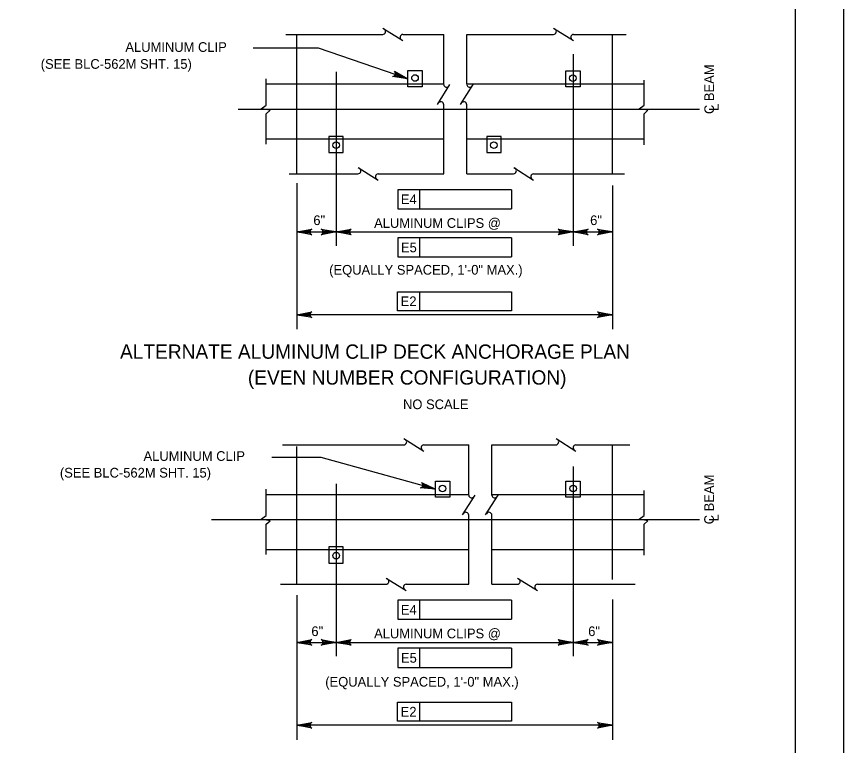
# Model space of a CAD drawing. Extents: x 638263 to 640391, y 293683 to 298655.
# Drawn here: x 639861.3 to 640117.5, y 295708.4 to 295934.1 of the extents above; entities that cross this region are included whole.
import ezdxf

# ---------------------------------------------------------------- set-up
doc = ezdxf.new("R2010")
doc.units = 0
for name, color, linetype in [('2', 7, 'Continuous'), ('3', 7, 'Continuous'), ('4', 7, 'Continuous'), ('8', 7, 'Continuous'), ('9', 7, 'Continuous'), ('PLT-BNDY', 7, 'Continuous')]:
    doc.layers.add(name, color=color, linetype=linetype)

msp = doc.modelspace()

# ---------------------------------------------------------------- linework, layer by layer
at = {"layer": '2'}
for p, q in [((640102.46, 296044.46), (640102.46, 295480.46)), ((639948.08, 295885.4), (639948.08, 295928.58)), ((640045.92, 295885.4), (640045.92, 295928.58)), ((639948.08, 295758.28), (639948.08, 295800.94)), ((640045.92, 295759.8), (640045.92, 295801.5))]:
    msp.add_line(p, q, dxfattribs=at)
at = {"layer": '3'}
for p, q in [((639974.77, 295930.52), (639980.92, 295926.65)), ((640027.67, 295930.52), (640033.82, 295926.65)), ((639944.64, 295928.58), (639974.69, 295928.58)), ((639980.91, 295928.58), (639993.61, 295928.58)), ((639993.61, 295913.01), (639993.61, 295928.58)), ((640000.76, 295913.01), (640000.76, 295928.58)), ((640000.76, 295928.58), (640027.59, 295928.58)), ((640033.81, 295928.58), (640050.15, 295928.58)), ((639938.58, 295906.7), (639938.58, 295914.8)), ((640055.66, 295906.7), (640055.66, 295914.42)), ((639938.58, 295913.23), (639993.61, 295913.23)), ((639991.67, 295906.86), (639995.54, 295913.02)), ((639998.83, 295906.86), (640002.7, 295913.02)), ((640000.76, 295913.23), (640055.66, 295913.23)), ((639937.04, 295905.51), (639938.58, 295906.7)), ((639993.61, 295885.4), (639993.61, 295906.79)), ((640000.76, 295885.4), (640000.76, 295906.79)), ((640054.12, 295905.51), (640055.66, 295906.7)), ((639939.8, 295905.08), (639937.04, 295905.51)), ((639938.58, 295903.99), (639939.8, 295905.08)), ((639938.58, 295894.57), (639938.58, 295903.99)), ((640056.88, 295905.08), (640054.12, 295905.51)), ((640055.66, 295903.99), (640056.88, 295905.08)), ((640055.66, 295894.38), (640055.66, 295903.99)), ((639993.61, 295896.11), (639938.58, 295896.11)), ((640055.66, 295896.11), (640000.76, 295896.11)), ((639945.69, 295885.4), (639967.04, 295885.4)), ((639967.11, 295887.33), (639973.27, 295883.46)), ((639973.26, 295885.4), (639993.61, 295885.4)), ((640000.76, 295885.4), (640015.22, 295885.4)), ((640015.29, 295887.33), (640021.45, 295883.46)), ((640021.44, 295885.4), (640049.62, 295885.4)), ((639981.29, 295803.4), (639987.45, 295799.53)), ((640028.41, 295803.4), (640034.57, 295799.53)), ((639943.68, 295801.46), (639981.22, 295801.46)), ((639987.44, 295801.46), (640001.37, 295801.46)), ((640001.37, 295785.88), (640001.37, 295801.46)), ((640008.53, 295801.46), (640028.34, 295801.46)), ((640008.53, 295785.88), (640008.53, 295801.46)), ((640034.56, 295801.46), (640051.22, 295801.46)), ((639938.58, 295779.58), (639938.58, 295787.68)), ((639938.58, 295786.11), (640001.37, 295786.11)), ((639999.43, 295779.74), (640003.3, 295785.9)), ((640006.59, 295779.74), (640010.46, 295785.9)), ((640008.53, 295786.11), (640055.66, 295786.11)), ((640055.66, 295779.58), (640055.66, 295787.3)), ((639937.04, 295778.39), (639938.58, 295779.58)), ((639939.8, 295777.96), (639937.04, 295778.39)), ((639938.58, 295776.87), (639939.8, 295777.96)), ((640001.37, 295758.28), (640001.37, 295779.67)), ((640008.53, 295758.28), (640008.53, 295779.67)), ((640054.12, 295778.39), (640055.66, 295779.58)), ((640056.88, 295777.96), (640054.12, 295778.39)), ((640055.66, 295776.87), (640056.88, 295777.96)), ((639938.58, 295767.45), (639938.58, 295776.87)), ((640055.66, 295767.26), (640055.66, 295776.87)), ((640001.37, 295768.99), (639938.58, 295768.99)), ((640055.66, 295768.99), (640008.53, 295768.99)), ((639975.79, 295760.21), (639981.95, 295756.34)), ((640016.49, 295760.21), (640022.65, 295756.34)), ((639942.99, 295758.28), (639975.72, 295758.28)), ((639981.94, 295758.28), (640001.37, 295758.28)), ((640008.53, 295758.28), (640016.42, 295758.28)), ((640022.64, 295758.28), (640052.96, 295758.28))]:
    msp.add_line(p, q, dxfattribs=at)
for centre in [(639984.71, 295915.07), (640033.63, 295915.01), (639960.25, 295894.26), (640009.17, 295894.26), (639993.26, 295787.95), (640033.69, 295787.95), (639960.25, 295767.14)]:
    msp.add_circle(centre, 1.02, dxfattribs=at)
for centre, start, end in [((639974.69, 295929.49), 270, 60), ((640027.59, 295929.49), 270, 60), ((639980.99, 295927.68), 95.3286, 237.8672), ((640033.89, 295927.68), 95.3286, 237.8672), ((639994.51, 295913.09), 185.3286, 327.8672), ((640001.67, 295913.09), 185.3286, 327.8672), ((639992.7, 295906.79), 0, 150), ((639999.85, 295906.79), 0, 150), ((639967.04, 295886.31), 270, 60), ((639973.34, 295884.49), 95.3286, 237.8672), ((640015.22, 295886.31), 270, 60), ((640021.52, 295884.49), 95.3286, 237.8672), ((639981.22, 295802.37), 270, 60), ((639987.52, 295800.56), 95.3286, 237.8672), ((640028.34, 295802.37), 270, 60), ((640034.64, 295800.56), 95.3286, 237.8672), ((640002.27, 295785.97), 185.3286, 327.8672), ((640009.43, 295785.97), 185.3286, 327.8672), ((640000.46, 295779.67), 0, 150), ((640007.62, 295779.67), 0, 150), ((639975.72, 295759.19), 270, 60), ((640016.42, 295759.19), 270, 60), ((639982.02, 295757.37), 95.3286, 237.8672), ((640022.72, 295757.37), 95.3286, 237.8672)]:
    msp.add_arc(centre, 0.909, start, end, dxfattribs=at)
at = {"layer": '4'}
for p, q in [((639954.77, 295924.32), (639934.55, 295924.32)), ((640072.85, 295905.34), (639929.93, 295905.34)), ((639979.35, 295880.48), (639979.35, 295874.57)), ((639986.24, 295880.48), (639979.35, 295880.48)), ((639986.24, 295874.57), (639986.24, 295880.48)), ((640014.65, 295880.48), (639986.24, 295880.48)), ((640014.65, 295880.48), (640014.65, 295874.57)), ((639948.08, 295876.08), (639948.08, 295837.24)), ((640045.92, 295876.08), (640045.92, 295837.24)), ((639979.35, 295874.57), (640014.65, 295874.57)), ((639948.08, 295867.4), (639960.31, 295867.4)), ((640033.69, 295867.4), (640045.92, 295867.4)), ((639979.35, 295865.57), (639979.35, 295859.67)), ((639986.24, 295865.57), (639979.35, 295865.57)), ((640014.65, 295865.57), (639986.24, 295865.57)), ((639986.24, 295859.67), (639986.24, 295865.57)), ((640014.65, 295865.57), (640014.65, 295859.67)), ((639979.35, 295859.67), (640014.65, 295859.67)), ((639979.31, 295848.89), (639986.2, 295848.89)), ((639979.31, 295842.99), (639979.31, 295848.89)), ((639986.2, 295842.99), (639986.2, 295848.89)), ((639986.2, 295848.89), (640014.61, 295848.89)), ((640014.61, 295848.89), (640014.61, 295842.99)), ((640045.92, 295841.74), (639948.08, 295841.74)), ((640014.61, 295842.99), (639979.31, 295842.99)), ((639955.6, 295797.56), (639940.34, 295797.56)), ((640072.85, 295778.22), (639921.63, 295778.22)), ((639979.35, 295753.36), (639979.35, 295747.45)), ((639986.24, 295753.36), (639979.35, 295753.36)), ((639986.24, 295747.45), (639986.24, 295753.36)), ((640014.65, 295753.36), (639986.24, 295753.36)), ((640014.65, 295753.36), (640014.65, 295747.45)), ((639948.08, 295748.96), (639948.08, 295710.12)), ((639979.35, 295747.45), (640014.65, 295747.45)), ((640045.92, 295748.96), (640045.92, 295710.12)), ((639948.08, 295740.27), (639960.31, 295740.27)), ((640033.69, 295740.27), (640045.92, 295740.27)), ((639979.35, 295738.45), (639979.35, 295732.55)), ((639986.24, 295738.45), (639979.35, 295738.45)), ((640014.65, 295738.45), (639986.24, 295738.45)), ((639986.24, 295732.55), (639986.24, 295738.45)), ((640014.65, 295738.45), (640014.65, 295732.55)), ((639979.35, 295732.55), (640014.65, 295732.55)), ((639979.31, 295721.77), (639986.13, 295721.78)), ((639979.31, 295715.87), (639979.31, 295721.77)), ((639986.13, 295721.78), (640014.56, 295721.8)), ((639986.2, 295715.87), (639986.2, 295721.77)), ((640014.61, 295721.77), (640014.61, 295715.87)), ((640045.92, 295714.62), (639948.08, 295714.62)), ((640014.61, 295715.87), (639979.31, 295715.87))]:
    msp.add_line(p, q, dxfattribs=at)
for points in [[(639982.48, 295914.85), (639954.77, 295924.32)], [(639982.48, 295914.85), (639977.78, 295915.53), (639978.2, 295915.65), (639978.48, 295915.88), (639978.63, 295916.16), (639978.68, 295916.47), (639978.61, 295916.83), (639978.35, 295917.18), (639982.48, 295914.85), (639978.61, 295916.83), (639978.68, 295916.47), (639982.48, 295914.85), (639978.63, 295916.16), (639978.48, 295915.88), (639982.48, 295914.85), (639978.2, 295915.65)], [(639948.08, 295867.4), (639952.74, 295868.27), (639952.38, 295868.02), (639952.2, 295867.71), (639952.14, 295867.4), (639952.2, 295867.08), (639952.38, 295866.77), (639952.74, 295866.52), (639948.08, 295867.4), (639952.38, 295866.77), (639952.2, 295867.08), (639948.08, 295867.4), (639952.14, 295867.4), (639952.2, 295867.71), (639948.08, 295867.4), (639952.38, 295868.02)], [(639960.31, 295867.4), (639955.65, 295866.52), (639956.01, 295866.77), (639956.19, 295867.08), (639956.25, 295867.4), (639956.19, 295867.71), (639956.01, 295868.02), (639955.65, 295868.27), (639960.31, 295867.4), (639956.01, 295868.02), (639956.19, 295867.71), (639960.31, 295867.4), (639956.25, 295867.4), (639956.19, 295867.08), (639960.31, 295867.4), (639956.01, 295866.77)], [(639960.31, 295867.4), (639964.97, 295868.27), (639964.61, 295868.02), (639964.43, 295867.71), (639964.37, 295867.4), (639964.43, 295867.08), (639964.61, 295866.77), (639964.97, 295866.52), (639960.31, 295867.4), (639964.61, 295866.77), (639964.43, 295867.08), (639960.31, 295867.4), (639964.37, 295867.4), (639964.43, 295867.71), (639960.31, 295867.4), (639964.61, 295868.02)], [(640033.69, 295867.4), (640029.03, 295866.52), (640029.39, 295866.77), (640029.57, 295867.08), (640029.63, 295867.4), (640029.57, 295867.71), (640029.39, 295868.02), (640029.03, 295868.27), (640033.69, 295867.4), (640029.39, 295868.02), (640029.57, 295867.71), (640033.69, 295867.4), (640029.63, 295867.4), (640029.57, 295867.08), (640033.69, 295867.4), (640029.39, 295866.77)], [(640033.69, 295867.4), (640038.35, 295868.27), (640037.99, 295868.02), (640037.81, 295867.71), (640037.75, 295867.4), (640037.81, 295867.08), (640037.99, 295866.77), (640038.35, 295866.52), (640033.69, 295867.4), (640037.99, 295866.77), (640037.81, 295867.08), (640033.69, 295867.4), (640037.75, 295867.4), (640037.81, 295867.71), (640033.69, 295867.4), (640037.99, 295868.02)], [(640045.92, 295867.4), (640041.26, 295866.52), (640041.62, 295866.77), (640041.8, 295867.08), (640041.86, 295867.4), (640041.8, 295867.71), (640041.62, 295868.02), (640041.26, 295868.27), (640045.92, 295867.4), (640041.62, 295868.02), (640041.8, 295867.71), (640045.92, 295867.4), (640041.86, 295867.4), (640041.8, 295867.08), (640045.92, 295867.4), (640041.62, 295866.77)], [(639948.08, 295841.74), (639952.74, 295842.61), (639952.38, 295842.36), (639952.2, 295842.05), (639952.14, 295841.74), (639952.2, 295841.43), (639952.38, 295841.11), (639952.74, 295840.87), (639948.08, 295841.74), (639952.38, 295841.11), (639952.2, 295841.43), (639948.08, 295841.74), (639952.14, 295841.74), (639952.2, 295842.05), (639948.08, 295841.74), (639952.38, 295842.36)], [(640045.92, 295841.74), (640041.26, 295840.87), (640041.62, 295841.11), (640041.8, 295841.43), (640041.86, 295841.74), (640041.8, 295842.05), (640041.62, 295842.36), (640041.26, 295842.61), (640045.92, 295841.74), (640041.62, 295842.36), (640041.8, 295842.05), (640045.92, 295841.74), (640041.86, 295841.74), (640041.8, 295841.43), (640045.92, 295841.74), (640041.62, 295841.11)], [(639991.03, 295787.72), (639955.6, 295797.56)], [(639991.03, 295787.72), (639986.3, 295788.13), (639986.72, 295788.27), (639986.98, 295788.52), (639987.12, 295788.81), (639987.15, 295789.13), (639987.05, 295789.48), (639986.77, 295789.81), (639991.03, 295787.72), (639987.05, 295789.48), (639987.15, 295789.13), (639991.03, 295787.72), (639987.12, 295788.81), (639986.98, 295788.52), (639991.03, 295787.72), (639986.72, 295788.27)], [(639948.08, 295740.27), (639952.74, 295741.15), (639952.38, 295740.9), (639952.2, 295740.59), (639952.14, 295740.27), (639952.2, 295739.96), (639952.38, 295739.65), (639952.74, 295739.4), (639948.08, 295740.27), (639952.38, 295739.65), (639952.2, 295739.96), (639948.08, 295740.27), (639952.14, 295740.27), (639952.2, 295740.59), (639948.08, 295740.27), (639952.38, 295740.9)], [(639960.31, 295740.27), (639955.65, 295739.4), (639956.01, 295739.65), (639956.19, 295739.96), (639956.25, 295740.27), (639956.19, 295740.59), (639956.01, 295740.9), (639955.65, 295741.15), (639960.31, 295740.27), (639956.01, 295740.9), (639956.19, 295740.59), (639960.31, 295740.27), (639956.25, 295740.27), (639956.19, 295739.96), (639960.31, 295740.27), (639956.01, 295739.65)], [(639960.31, 295740.27), (639964.97, 295741.15), (639964.61, 295740.9), (639964.43, 295740.59), (639964.37, 295740.27), (639964.43, 295739.96), (639964.61, 295739.65), (639964.97, 295739.4), (639960.31, 295740.27), (639964.61, 295739.65), (639964.43, 295739.96), (639960.31, 295740.27), (639964.37, 295740.27), (639964.43, 295740.59), (639960.31, 295740.27), (639964.61, 295740.9)], [(640033.69, 295740.27), (640029.03, 295739.4), (640029.39, 295739.65), (640029.57, 295739.96), (640029.63, 295740.27), (640029.57, 295740.59), (640029.39, 295740.9), (640029.03, 295741.15), (640033.69, 295740.27), (640029.39, 295740.9), (640029.57, 295740.59), (640033.69, 295740.27), (640029.63, 295740.27), (640029.57, 295739.96), (640033.69, 295740.27), (640029.39, 295739.65)], [(640033.69, 295740.27), (640038.35, 295741.15), (640037.99, 295740.9), (640037.81, 295740.59), (640037.75, 295740.27), (640037.81, 295739.96), (640037.99, 295739.65), (640038.35, 295739.4), (640033.69, 295740.27), (640037.99, 295739.65), (640037.81, 295739.96), (640033.69, 295740.27), (640037.75, 295740.27), (640037.81, 295740.59), (640033.69, 295740.27), (640037.99, 295740.9)], [(640045.92, 295740.27), (640041.26, 295739.4), (640041.62, 295739.65), (640041.8, 295739.96), (640041.86, 295740.27), (640041.8, 295740.59), (640041.62, 295740.9), (640041.26, 295741.15), (640045.92, 295740.27), (640041.62, 295740.9), (640041.8, 295740.59), (640045.92, 295740.27), (640041.86, 295740.27), (640041.8, 295739.96), (640045.92, 295740.27), (640041.62, 295739.65)], [(639948.08, 295714.62), (639952.74, 295715.49), (639952.38, 295715.24), (639952.2, 295714.93), (639952.14, 295714.62), (639952.2, 295714.31), (639952.38, 295713.99), (639952.74, 295713.74), (639948.08, 295714.62), (639952.38, 295713.99), (639952.2, 295714.31), (639948.08, 295714.62), (639952.14, 295714.62), (639952.2, 295714.93), (639948.08, 295714.62), (639952.38, 295715.24)], [(640045.92, 295714.62), (640041.26, 295713.74), (640041.62, 295713.99), (640041.8, 295714.31), (640041.86, 295714.62), (640041.8, 295714.93), (640041.62, 295715.24), (640041.26, 295715.49), (640045.92, 295714.62), (640041.62, 295715.24), (640041.8, 295714.93), (640045.92, 295714.62), (640041.86, 295714.62), (640041.8, 295714.31), (640045.92, 295714.62), (640041.62, 295713.99)]]:
    msp.add_lwpolyline(points, dxfattribs=at)
for points in [[(639982.48, 295914.85), (639982.37, 295914.91), (639982.35, 295914.86)], [(639991.03, 295787.72), (639990.92, 295787.78), (639990.91, 295787.73)]]:
    msp.add_lwpolyline(points, close=True, dxfattribs=at)
at = {"layer": '8'}
for p, q in [((640033.69, 295922.45), (640033.69, 295863.14)), ((639960.31, 295916.98), (639960.31, 295863.14)), ((640033.63, 295915.01), (640033.63, 295915.01)), ((640050.48, 295913.23), (640050.48, 295913.23)), ((639942.75, 295896.11), (639942.75, 295896.11)), ((640041.02, 295896.11), (640041.02, 295896.11)), ((639960.25, 295894.26), (639960.25, 295894.26)), ((639948.08, 295882.48), (639948.08, 295863.14)), ((640045.92, 295881.78), (640045.92, 295863.14)), ((639960.31, 295867.4), (640033.69, 295867.4)), ((640033.69, 295794.75), (640033.69, 295736.02)), ((639960.31, 295789.43), (639960.31, 295736.02)), ((640050.48, 295786.11), (640050.48, 295786.11)), ((639942.75, 295768.99), (639942.75, 295768.99)), ((640041.02, 295768.99), (640041.02, 295768.99)), ((639960.25, 295767.14), (639960.25, 295767.14)), ((639948.08, 295754.94), (639948.08, 295736.02)), ((640045.92, 295753.55), (640045.92, 295736.02)), ((639960.31, 295740.27), (640033.69, 295740.27))]:
    msp.add_line(p, q, dxfattribs=at)
at = {"layer": '9'}
for p, q in [((639982.48, 295917.35), (639986.94, 295917.35)), ((639982.48, 295912.34), (639982.48, 295917.35)), ((639986.94, 295917.35), (639986.94, 295912.34)), ((640031.39, 295917.29), (640035.86, 295917.29)), ((640031.39, 295912.29), (640031.39, 295917.29)), ((640035.86, 295917.29), (640035.86, 295912.29)), ((639986.94, 295912.34), (639982.48, 295912.34)), ((640035.86, 295912.29), (640031.39, 295912.29)), ((639958.02, 295896.99), (639958.02, 295891.98)), ((639962.49, 295896.99), (639958.02, 295896.99)), ((639962.49, 295891.98), (639962.49, 295896.99)), ((640006.93, 295896.99), (640006.93, 295891.98)), ((640011.4, 295896.99), (640006.93, 295896.99)), ((640011.4, 295891.98), (640011.4, 295896.99)), ((639958.02, 295891.98), (639962.49, 295891.98)), ((640006.93, 295891.98), (640011.4, 295891.98)), ((639991.03, 295790.22), (639995.5, 295790.22)), ((639991.03, 295785.22), (639991.03, 295790.22)), ((639995.5, 295790.22), (639995.5, 295785.22)), ((640031.45, 295785.22), (640031.45, 295790.22)), ((640031.45, 295790.22), (640035.92, 295790.22)), ((640035.92, 295790.22), (640035.92, 295785.22)), ((639995.5, 295785.22), (639991.03, 295785.22)), ((640035.92, 295785.22), (640031.45, 295785.22)), ((639958.02, 295769.87), (639958.02, 295764.86)), ((639962.49, 295769.87), (639958.02, 295769.87)), ((639962.49, 295764.86), (639962.49, 295769.87)), ((639958.02, 295764.86), (639962.49, 295764.86))]:
    msp.add_line(p, q, dxfattribs=at)
at = {"layer": 'PLT-BNDY'}
msp.add_lwpolyline([(639276.46, 296059.46), (640117.46, 296059.46), (640117.46, 295465.46), (639276.46, 295465.46)], close=True, dxfattribs=at)

# ---------------------------------------------------------------- texts
at = {"layer": '4'}
for s, height, p in [('ALUMINUM CLIP', 3, (639894.97, 295923.16)), ('(SEE BLC-562M SHT. 15)', 3, (639868.75, 295917.92)), ('E4', 3, (639980.33, 295876)), ('6"', 3, (639953.21, 295869.52)), ('6"', 3, (640038.97, 295869.52)), ('ALUMINUM CLIPS @', 3, (639972.04, 295868.66)), ('E5', 3, (639980.36, 295861.1)), ('(EQUALLY SPACED, 1\'-0" MAX.)', 3, (639958.12, 295854.17)), ('E2', 3, (639980.27, 295844.42)), ('ALTERNATE ALUMINUM CLIP DECK ANCHORAGE PLAN', 4.4292, (639893.32, 295828.12)), ('(EVEN NUMBER CONFIGURATION)', 4.4292, (639932.93, 295820.11)), ('NO SCALE', 3, (639981, 295812.51)), ('ALUMINUM CLIP', 3, (639900.6, 295796.49)), ('(SEE BLC-562M SHT. 15)', 3, (639874.69, 295791.33)), ('E4', 3, (639980.33, 295748.88)), ('6"', 3, (639952.6, 295742.23)), ('ALUMINUM CLIPS @', 3, (639972.04, 295741.54)), ('6"', 3, (640038.37, 295742.23)), ('E5', 3, (639980.36, 295733.98)), ('(EQUALLY SPACED, 1\'-0" MAX.)', 3, (639956.9, 295726.58)), ('E2', 3, (639980.27, 295717.3))]:
    msp.add_text(s, height=height, dxfattribs=at).set_placement(p)
for s, p in [('C BEAM', (640077.36, 295903.9)), ('L', (640078.82, 295904.88)), ('C BEAM', (640077.32, 295776.85)), ('L', (640078.82, 295777.76))]:
    msp.add_text(s, height=3, rotation=90, dxfattribs=at).set_placement(p)

doc.saveas('drawing.dxf')
